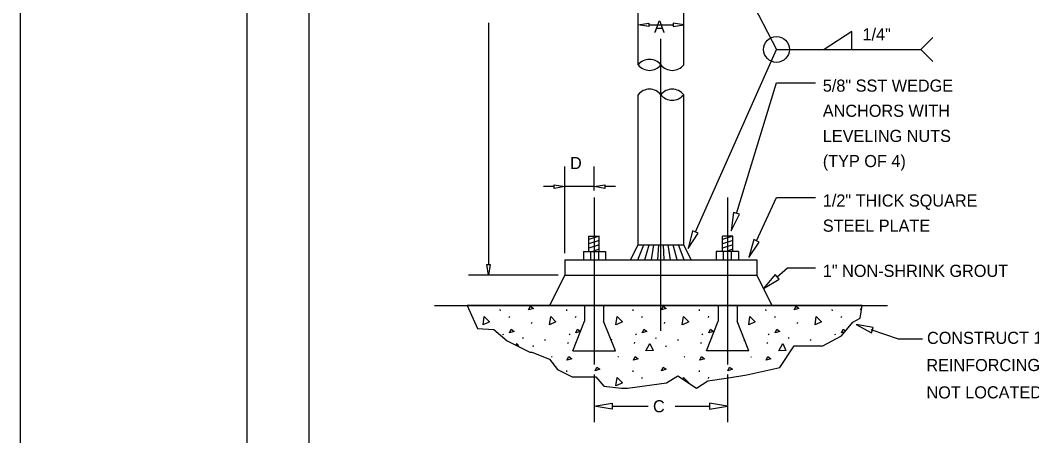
# Model space of a CAD drawing. Extents: x 2147138 to 2147698, y 2147153 to 2147515.
# Drawn here: x 2147137.8 to 2147237.7, y 2147408.1 to 2147449.2 of the extents above; entities that cross this region are included whole.
import ezdxf

# ---------------------------------------------------------------- set-up
doc = ezdxf.new("R2010")
doc.units = 0
for name, color, linetype in [('1', 7, 'Continuous'), ('CONSTRUCTION_CLASS', 7, 'Continuous'), ('G-DETL-ANNO-LW10', 7, 'Continuous'), ('G-DETL-CNTR', 7, 'Continuous'), ('G-DETL-HIDD', 7, 'Continuous'), ('G-DETL-LW10', 7, 'Continuous'), ('G-DETL-PATT', 7, 'Continuous'), ('PATTERN_CLASS', 7, 'Continuous')]:
    doc.layers.add(name, color=color, linetype=linetype)

msp = doc.modelspace()

# ---------------------------------------------------------------- linework, layer by layer
at = {"layer": '1'}
for p, q in [((2147185.197, 2147420.629), (2147185.212, 2147420.498)), ((2147188.031, 2147420.606), (2147188.206, 2147420.97)), ((2147188.497, 2147420.752), (2147188.031, 2147420.606)), ((2147188.206, 2147420.97), (2147188.497, 2147420.752)), ((2147191.759, 2147420.629), (2147191.774, 2147420.498)), ((2147198.321, 2147420.629), (2147198.335, 2147420.498)), ((2147201.155, 2147420.606), (2147201.329, 2147420.97)), ((2147201.621, 2147420.752), (2147201.155, 2147420.606)), ((2147201.329, 2147420.97), (2147201.621, 2147420.752)), ((2147204.882, 2147420.629), (2147204.897, 2147420.498)), ((2147211.444, 2147420.629), (2147211.459, 2147420.498)), ((2147214.278, 2147420.606), (2147214.453, 2147420.97)), ((2147214.744, 2147420.752), (2147214.278, 2147420.606)), ((2147214.453, 2147420.97), (2147214.744, 2147420.752)), ((2147218.006, 2147420.629), (2147218.02, 2147420.498)), ((2147220.84, 2147420.606), (2147220.945, 2147420.827)), ((2147220.914, 2147420.629), (2147220.84, 2147420.606)), ((2147183.53, 2147419.108), (2147183.646, 2147419.94)), ((2147184.167, 2147419.402), (2147183.544, 2147419.113)), ((2147183.646, 2147419.94), (2147184.167, 2147419.402)), ((2147186.106, 2147419.856), (2147186.164, 2147419.987)), ((2147188.32, 2147419.258), (2147188.378, 2147419.39)), ((2147190.092, 2147419.108), (2147190.207, 2147419.94)), ((2147190.729, 2147419.402), (2147190.106, 2147419.113)), ((2147190.207, 2147419.94), (2147190.729, 2147419.402)), ((2147192.667, 2147419.856), (2147192.726, 2147419.987)), ((2147196.654, 2147419.108), (2147196.769, 2147419.94)), ((2147197.291, 2147419.402), (2147196.667, 2147419.113)), ((2147196.769, 2147419.94), (2147197.291, 2147419.402)), ((2147199.229, 2147419.856), (2147199.287, 2147419.987)), ((2147201.443, 2147419.258), (2147201.501, 2147419.39)), ((2147203.215, 2147419.108), (2147203.331, 2147419.94)), ((2147203.852, 2147419.402), (2147203.229, 2147419.113)), ((2147203.331, 2147419.94), (2147203.852, 2147419.402)), ((2147205.791, 2147419.856), (2147205.849, 2147419.987)), ((2147209.777, 2147419.108), (2147209.893, 2147419.94)), ((2147210.414, 2147419.402), (2147209.791, 2147419.113)), ((2147209.893, 2147419.94), (2147210.414, 2147419.402)), ((2147212.352, 2147419.856), (2147212.411, 2147419.987)), ((2147214.566, 2147419.258), (2147214.625, 2147419.39)), ((2147216.339, 2147419.108), (2147216.454, 2147419.94)), ((2147216.976, 2147419.402), (2147216.352, 2147419.113)), ((2147216.454, 2147419.94), (2147216.976, 2147419.402)), ((2147218.914, 2147419.856), (2147218.972, 2147419.987)), ((2147185.467, 2147418.225), (2147185.525, 2147418.137)), ((2147186.135, 2147418.326), (2147186.31, 2147418.69)), ((2147186.601, 2147418.472), (2147186.135, 2147418.326)), ((2147186.31, 2147418.69), (2147186.601, 2147418.472)), ((2147192.028, 2147418.225), (2147192.087, 2147418.137)), ((2147192.696, 2147418.326), (2147192.871, 2147418.69)), ((2147193.163, 2147418.472), (2147192.696, 2147418.326)), ((2147192.871, 2147418.69), (2147193.163, 2147418.472)), ((2147198.59, 2147418.225), (2147198.648, 2147418.137)), ((2147199.258, 2147418.326), (2147199.433, 2147418.69)), ((2147199.724, 2147418.472), (2147199.258, 2147418.326)), ((2147199.433, 2147418.69), (2147199.724, 2147418.472)), ((2147205.152, 2147418.225), (2147205.21, 2147418.137)), ((2147205.82, 2147418.326), (2147205.995, 2147418.69)), ((2147206.286, 2147418.472), (2147205.82, 2147418.326)), ((2147205.995, 2147418.69), (2147206.286, 2147418.472)), ((2147211.713, 2147418.225), (2147211.772, 2147418.137)), ((2147212.381, 2147418.326), (2147212.556, 2147418.69)), ((2147212.848, 2147418.472), (2147212.381, 2147418.326)), ((2147212.556, 2147418.69), (2147212.848, 2147418.472)), ((2147218.275, 2147418.225), (2147218.333, 2147418.137)), ((2147218.943, 2147418.326), (2147219.118, 2147418.69)), ((2147219.266, 2147418.427), (2147218.943, 2147418.326)), ((2147219.118, 2147418.69), (2147219.345, 2147418.52)), ((2147186.797, 2147417.099), (2147186.892, 2147417.279)), ((2147186.892, 2147417.279), (2147187.023, 2147416.986)), ((2147187.429, 2147417.854), (2147187.487, 2147417.767)), ((2147189.645, 2147417.569), (2147189.704, 2147417.7)), ((2147191.918, 2147417.265), (2147191.976, 2147417.396)), ((2147196.207, 2147417.569), (2147196.265, 2147417.7)), ((2147198.479, 2147417.265), (2147198.538, 2147417.396)), ((2147199.622, 2147416.536), (2147200.016, 2147417.279)), ((2147200.016, 2147417.279), (2147200.321, 2147416.595)), ((2147200.552, 2147417.854), (2147200.61, 2147417.767)), ((2147202.769, 2147417.569), (2147202.827, 2147417.7)), ((2147205.041, 2147417.265), (2147205.1, 2147417.396)), ((2147209.33, 2147417.569), (2147209.389, 2147417.7)), ((2147211.603, 2147417.265), (2147211.661, 2147417.396)), ((2147212.746, 2147416.536), (2147213.139, 2147417.279)), ((2147213.139, 2147417.279), (2147213.445, 2147416.595)), ((2147213.675, 2147417.854), (2147213.734, 2147417.767)), ((2147215.892, 2147417.569), (2147215.95, 2147417.7)), ((2147188.465, 2147416.93), (2147188.524, 2147417.061)), ((2147200.321, 2147416.595), (2147199.637, 2147416.536)), ((2147201.589, 2147416.93), (2147201.647, 2147417.061)), ((2147213.445, 2147416.595), (2147212.76, 2147416.536)), ((2147214.758, 2147417.033), (2147214.77, 2147417.061)), ((2147190.286, 2147415.997), (2147190.345, 2147415.91)), ((2147191.816, 2147415.619), (2147191.991, 2147415.983)), ((2147192.282, 2147415.764), (2147191.816, 2147415.619)), ((2147191.991, 2147415.983), (2147192.282, 2147415.764)), ((2147196.848, 2147415.997), (2147196.906, 2147415.91)), ((2147198.378, 2147415.619), (2147198.552, 2147415.983)), ((2147198.844, 2147415.764), (2147198.378, 2147415.619)), ((2147198.552, 2147415.983), (2147198.844, 2147415.764)), ((2147203.41, 2147415.997), (2147203.468, 2147415.91)), ((2147204.939, 2147415.619), (2147205.114, 2147415.983)), ((2147205.405, 2147415.764), (2147204.939, 2147415.619)), ((2147205.114, 2147415.983), (2147205.405, 2147415.764)), ((2147209.971, 2147415.997), (2147210.03, 2147415.91)), ((2147211.501, 2147415.619), (2147211.676, 2147415.983)), ((2147211.967, 2147415.764), (2147211.501, 2147415.619)), ((2147211.676, 2147415.983), (2147211.967, 2147415.764)), ((2147191.759, 2147414.6), (2147191.774, 2147414.469)), ((2147194.593, 2147414.577), (2147194.768, 2147414.941)), ((2147195.059, 2147414.723), (2147194.593, 2147414.577)), ((2147194.768, 2147414.941), (2147195.059, 2147414.723)), ((2147198.321, 2147414.6), (2147198.335, 2147414.469)), ((2147201.155, 2147414.577), (2147201.329, 2147414.941)), ((2147201.621, 2147414.723), (2147201.155, 2147414.577)), ((2147201.329, 2147414.941), (2147201.621, 2147414.723)), ((2147204.882, 2147414.6), (2147204.897, 2147414.469)), ((2147207.716, 2147414.577), (2147207.891, 2147414.941)), ((2147208.182, 2147414.723), (2147207.716, 2147414.577)), ((2147207.891, 2147414.941), (2147208.182, 2147414.723)), ((2147211.444, 2147414.6), (2147211.445, 2147414.593)), ((2147196.654, 2147413.079), (2147196.769, 2147413.911)), ((2147197.291, 2147413.373), (2147196.667, 2147413.084)), ((2147196.769, 2147413.911), (2147197.291, 2147413.373)), ((2147199.229, 2147413.827), (2147199.287, 2147413.958)), ((2147201.498, 2147413.353), (2147201.501, 2147413.361)), ((2147203.307, 2147413.739), (2147203.331, 2147413.911)), ((2147203.331, 2147413.911), (2147203.846, 2147413.38)), ((2147205.791, 2147413.827), (2147205.849, 2147413.958))]:
    msp.add_line(p, q, dxfattribs=at)
at = {"layer": 'CONSTRUCTION_CLASS'}
for p, q in [((2147137.785, 2147515.078), (2147137.785, 2147152.807)), ((2147160.204, 2147160.521), (2147160.204, 2147507.94))]:
    msp.add_line(p, q, dxfattribs=at)
at = {"layer": 'G-DETL-ANNO-LW10'}
for p, q in [((2147207.743, 2147455.56), (2147212.519, 2147446.356)), ((2147184.06, 2147448.99), (2147184.06, 2147425.089)), ((2147199.903, 2147448.794), (2147202.295, 2147448.794)), ((2147219.952, 2147448.141), (2147217.245, 2147446.356)), ((2147219.952, 2147446.356), (2147219.952, 2147448.141)), ((2147226.794, 2147446.356), (2147227.988, 2147447.549)), ((2147204.506, 2147428.309), (2147212.519, 2147446.356)), ((2147212.519, 2147446.356), (2147216.373, 2147446.356)), ((2147216.373, 2147446.356), (2147226.794, 2147446.356)), ((2147226.794, 2147446.356), (2147227.988, 2147445.162)), ((2147208.566, 2147430.144), (2147212.519, 2147443.069)), ((2147212.519, 2147443.069), (2147216.373, 2147443.069)), ((2147191.617, 2147426.221), (2147191.617, 2147434.765)), ((2147194.502, 2147432.409), (2147194.502, 2147434.765)), ((2147190.562, 2147432.788), (2147189.508, 2147432.788)), ((2147194.502, 2147432.788), (2147191.617, 2147432.788)), ((2147196.611, 2147432.788), (2147195.557, 2147432.788)), ((2147210.549, 2147427.42), (2147212.519, 2147431.705)), ((2147212.519, 2147431.705), (2147216.373, 2147431.705)), ((2147212.602, 2147423.879), (2147213.612, 2147424.75)), ((2147213.612, 2147424.75), (2147216.373, 2147424.75)), ((2147190.93, 2147424.035), (2147182.083, 2147424.035)), ((2147221.841, 2147418.648), (2147224.544, 2147417.722)), ((2147224.544, 2147417.722), (2147226.95, 2147417.722)), ((2147194.502, 2147414.194), (2147194.502, 2147409.484)), ((2147207.696, 2147414.194), (2147207.696, 2147409.484)), ((2147196.294, 2147411.091), (2147199.83, 2147411.091)), ((2147202.525, 2147411.091), (2147205.904, 2147411.091))]:
    msp.add_line(p, q, dxfattribs=at)
for points in [[(2147199.903, 2147448.97), (2147199.903, 2147448.618), (2147198.849, 2147448.794)], [(2147202.295, 2147448.97), (2147202.295, 2147448.618), (2147203.349, 2147448.794)], [(2147190.562, 2147432.964), (2147191.617, 2147432.788), (2147190.562, 2147432.612)], [(2147195.557, 2147432.612), (2147194.502, 2147432.788), (2147195.557, 2147432.964)], [(2147208.851, 2147430.057), (2147208.28, 2147430.231), (2147208.042, 2147428.43)], [(2147204.779, 2147428.188), (2147204.233, 2147428.431), (2147203.778, 2147426.672)], [(2147210.821, 2147427.296), (2147210.278, 2147427.545), (2147209.801, 2147425.792)], [(2147184.236, 2147425.089), (2147184.06, 2147424.035), (2147183.885, 2147425.089)], [(2147212.797, 2147423.653), (2147212.407, 2147424.105), (2147211.244, 2147422.709)], [(2147221.895, 2147418.332), (2147222.077, 2147418.865), (2147220.387, 2147419.146)], [(2147196.294, 2147411.39), (2147196.294, 2147410.792), (2147194.502, 2147411.091)], [(2147205.904, 2147411.39), (2147205.904, 2147410.792), (2147207.696, 2147411.091)]]:
    msp.add_lwpolyline(points, close=True, dxfattribs=at)
msp.add_circle((2147212.519, 2147446.356), 1.275, dxfattribs=at)
at = {"layer": 'G-DETL-CNTR'}
for p, q in [((2147201.099, 2147418.516), (2147201.099, 2147447.422)), ((2147194.502, 2147431.723), (2147194.502, 2147415.194)), ((2147207.696, 2147431.723), (2147207.696, 2147415.194))]:
    msp.add_line(p, q, dxfattribs=at)
at = {"layer": 'G-DETL-HIDD'}
for p, q in [((2147193.565, 2147421.035), (2147193.565, 2147419.468)), ((2147195.44, 2147421.035), (2147195.44, 2147419.468)), ((2147206.758, 2147421.035), (2147206.758, 2147419.468)), ((2147208.633, 2147421.035), (2147208.633, 2147419.468)), ((2147192.402, 2147416.555), (2147193.565, 2147419.468)), ((2147196.602, 2147416.555), (2147195.44, 2147419.468)), ((2147205.596, 2147416.555), (2147206.758, 2147419.468)), ((2147209.796, 2147416.555), (2147208.633, 2147419.468)), ((2147192.402, 2147416.555), (2147196.602, 2147416.555)), ((2147209.796, 2147416.555), (2147205.596, 2147416.555))]:
    msp.add_line(p, q, dxfattribs=at)
at = {"layer": 'G-DETL-LW10'}
for p, q in [((2147198.849, 2147444.832), (2147198.849, 2147462.574)), ((2147203.349, 2147444.832), (2147203.349, 2147462.574)), ((2147198.849, 2147427.035), (2147198.849, 2147441.881)), ((2147203.349, 2147427.035), (2147203.349, 2147441.881)), ((2147193.991, 2147427.875), (2147195.013, 2147427.875)), ((2147195.013, 2147427.875), (2147193.991, 2147427.555)), ((2147193.991, 2147426.386), (2147193.991, 2147427.875)), ((2147195.013, 2147427.446), (2147193.991, 2147427.127)), ((2147195.013, 2147426.386), (2147195.013, 2147427.875)), ((2147207.185, 2147426.386), (2147207.185, 2147427.875)), ((2147208.207, 2147427.875), (2147207.185, 2147427.555)), ((2147208.207, 2147427.875), (2147207.185, 2147427.875)), ((2147208.207, 2147427.446), (2147207.185, 2147427.127)), ((2147208.207, 2147426.386), (2147208.207, 2147427.875)), ((2147193.436, 2147426.386), (2147193.436, 2147425.535)), ((2147193.436, 2147426.386), (2147195.639, 2147426.386)), ((2147195.013, 2147427.018), (2147193.991, 2147426.699)), ((2147194.139, 2147426.386), (2147194.139, 2147425.535)), ((2147195.013, 2147426.59), (2147194.357, 2147426.385)), ((2147194.936, 2147426.386), (2147194.936, 2147425.535)), ((2147195.639, 2147426.386), (2147195.639, 2147425.535)), ((2147198.082, 2147425.535), (2147198.849, 2147427.035)), ((2147198.83, 2147425.535), (2147199.409, 2147427.035)), ((2147198.849, 2147427.035), (2147203.349, 2147427.035)), ((2147199.521, 2147425.535), (2147199.925, 2147427.035)), ((2147200.173, 2147425.535), (2147200.413, 2147427.035)), ((2147200.804, 2147425.535), (2147200.885, 2147427.035)), ((2147201.427, 2147425.535), (2147201.351, 2147427.035)), ((2147202.058, 2147425.535), (2147201.822, 2147427.035)), ((2147202.709, 2147425.535), (2147202.309, 2147427.035)), ((2147203.398, 2147425.535), (2147202.825, 2147427.035)), ((2147204.099, 2147425.535), (2147203.349, 2147427.035)), ((2147206.559, 2147426.386), (2147206.559, 2147425.535)), ((2147208.762, 2147426.386), (2147206.559, 2147426.386)), ((2147208.207, 2147427.018), (2147207.185, 2147426.699)), ((2147207.262, 2147426.386), (2147207.262, 2147425.535)), ((2147208.207, 2147426.59), (2147207.551, 2147426.385)), ((2147208.059, 2147426.386), (2147208.059, 2147425.535)), ((2147208.762, 2147426.386), (2147208.762, 2147425.535)), ((2147191.617, 2147425.535), (2147191.617, 2147424.035)), ((2147191.617, 2147425.535), (2147210.581, 2147425.535)), ((2147210.581, 2147425.535), (2147210.581, 2147424.035)), ((2147190.117, 2147421.035), (2147191.617, 2147424.035)), ((2147191.617, 2147424.035), (2147210.581, 2147424.035)), ((2147212.081, 2147421.035), (2147210.581, 2147424.035)), ((2147178.72, 2147421.035), (2147223.478, 2147421.035))]:
    msp.add_line(p, q, dxfattribs=at)
for centre, start, end in [((2147199.974, 2147443.942), 38.3518, 141.6482), ((2147199.974, 2147445.722), 218.3518, 321.6482), ((2147202.224, 2147445.722), 218.3518, 321.6482), ((2147199.974, 2147440.991), 38.3518, 141.6482), ((2147202.224, 2147440.991), 38.3518, 141.6482), ((2147202.224, 2147442.772), 218.3518, 321.6482)]:
    msp.add_arc(centre, 1.435, start, end, dxfattribs=at)
at = {"layer": 'G-DETL-PATT'}
for p, q in [((2147181.948, 2147421.035), (2147182.964, 2147418.76)), ((2147220.979, 2147421.035), (2147181.948, 2147421.035)), ((2147181.948, 2147421.035), (2147181.948, 2147421.035)), ((2147220.776, 2147419.776), (2147220.979, 2147421.035)), ((2147218.946, 2147418.049), (2147220.064, 2147419.37)), ((2147220.064, 2147419.37), (2147220.776, 2147419.776)), ((2147182.964, 2147418.76), (2147184.591, 2147418.659)), ((2147184.591, 2147418.659), (2147185.912, 2147417.541)), ((2147185.912, 2147417.541), (2147188.148, 2147416.424)), ((2147217.117, 2147417.033), (2147218.946, 2147418.049)), ((2147188.148, 2147416.424), (2147188.351, 2147416.424)), ((2147188.351, 2147416.424), (2147190.079, 2147415.712)), ((2147212.848, 2147414.9), (2147214.271, 2147417.033)), ((2147214.271, 2147417.033), (2147217.117, 2147417.033)), ((2147190.079, 2147415.712), (2147190.892, 2147414.696)), ((2147190.892, 2147414.696), (2147192.315, 2147413.985)), ((2147207.765, 2147413.883), (2147209.595, 2147414.188)), ((2147209.595, 2147414.188), (2147212.848, 2147414.9)), ((2147192.315, 2147413.985), (2147194.653, 2147413.985)), ((2147194.653, 2147413.985), (2147195.466, 2147413.071)), ((2147197.804, 2147412.867), (2147201.667, 2147413.375)), ((2147201.667, 2147413.375), (2147202.785, 2147414.087)), ((2147202.785, 2147414.087), (2147204.614, 2147412.867)), ((2147204.614, 2147412.867), (2147205.732, 2147413.579)), ((2147205.732, 2147413.579), (2147207.765, 2147413.883)), ((2147195.466, 2147413.071), (2147197.194, 2147412.867)), ((2147197.194, 2147412.867), (2147197.804, 2147412.867))]:
    msp.add_line(p, q, dxfattribs=at)
for centre, start, end in [((2147199.974, 2147443.942), 38.3518, 141.6482), ((2147199.974, 2147445.722), 218.3518, 321.6482), ((2147202.224, 2147440.991), 38.3518, 141.6482), ((2147202.224, 2147442.772), 218.3518, 321.6482)]:
    msp.add_arc(centre, 1.435, start, end, dxfattribs=at)
at = {"layer": 'PATTERN_CLASS'}
msp.add_line((2147166.29, 2147503.536), (2147166.29, 2147351.266), dxfattribs=at)

# ---------------------------------------------------------------- texts
at = {"layer": 'G-DETL-ANNO-LW10'}
for s, p in [('A', (2147200.42, 2147448.016)), ('1/4"', (2147221.024, 2147447.253)), ('5/8" SST WEDGE', (2147217.099, 2147442.18)), ('ANCHORS WITH ', (2147217.099, 2147439.693)), ('LEVELING NUTS', (2147217.099, 2147437.206)), ('D', (2147192.119, 2147434.522)), ('(TYP OF 4)', (2147217.099, 2147434.719)), ('1/2" THICK SQUARE', (2147217.099, 2147430.816)), ('STEEL PLATE', (2147217.099, 2147428.329)), ('1" NON-SHRINK GROUT', (2147217.099, 2147423.861)), ('C', (2147200.316, 2147410.468))]:
    msp.add_text(s, height=1.2, dxfattribs=at).set_placement(p)
for s, p in [('CONSTRUCT 18" x 18" x 6" CONC BASE WITH # 4', (2147227.397, 2147417.227)), ('REINFORCING STEEL @ 5" OCEW IF SUPPORT IS', (2147227.337, 2147414.531)), ('NOT LOCATED ON AN EXISTING SLAB.', (2147227.346, 2147411.836))]:
    msp.add_text(s, height=1.2, rotation=0.08956, dxfattribs=at).set_placement(p)

doc.saveas('drawing.dxf')
